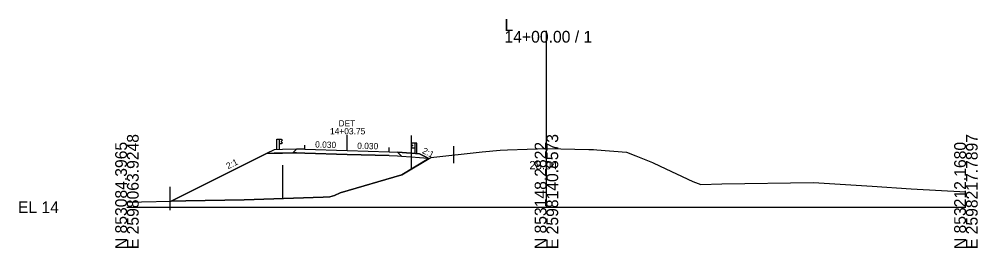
# Model space of a CAD drawing. Extents: x -26 to 1203, y -10 to 9526.
# Drawn here: x -25.7 to 202.8, y 3990.3 to 4044.9 of the extents above; entities that cross this region are included whole.
import ezdxf

# ---------------------------------------------------------------- set-up
doc = ezdxf.new("R2010")
doc.units = 0
for name, color, linetype in [('Exist Cross Section Cell', 7, 'Continuous'), ('Exist XS Center Line Elevation Label', 7, 'Continuous'), ('Exist XS Ground Line', 7, 'Continuous'), ('Prop XS Alignment Label', 7, 'Continuous'), ('Prop XS Earthwork Shape', 7, 'Continuous'), ('Prop XS EOT Tick Mark', 7, 'Continuous'), ('Prop XS Exc Vertical Line 1', 7, 'Continuous'), ('Prop XS Exc Vertical Line 2', 7, 'Continuous'), ('Prop XS Finish Grade', 7, 'Continuous'), ('Prop XS Finish Grade Earthwork', 7, 'Continuous'), ('Prop XS Finish Grade Paved Shoulder', 7, 'Continuous'), ('Prop XS Finish Grade Pavement', 7, 'Continuous'), ('Prop XS Guardrail', 7, 'Continuous'), ('Prop XS Pvmt Edge Slope', 7, 'Continuous'), ('Prop XS SE Text', 7, 'Continuous'), ('Prop XS Side Slope Text', 7, 'Continuous'), ('Prop XS Station Labels', 7, 'Continuous'), ('Prop XS Subgrade Earthwork', 7, 'Continuous'), ('Scratch_Level_1', 7, 'Continuous'), ('Scratch_Level_2', 7, 'Continuous')]:
    doc.layers.add(name, color=color, linetype=linetype)

msp = doc.modelspace()

# ---------------------------------------------------------------- linework, layer by layer
at = {"layer": 'Exist Cross Section Cell'}
for p, q in [((100, 4000), (100, 4042.11)), ((0, 4000), (100, 4000)), ((100, 4000), (200, 4000))]:
    msp.add_line(p, q, dxfattribs=at)
at = {"layer": 'Exist XS Ground Line'}
for p, q in [((72.42, 4011.9), (84.69, 4013.21)), ((84.69, 4013.21), (88.97, 4013.65)), ((88.97, 4013.65), (90.75, 4013.71)), ((90.75, 4013.71), (100.08, 4014.04)), ((100.08, 4014.04), (110.08, 4013.82)), ((110.08, 4013.82), (111.25, 4013.8)), ((111.25, 4013.8), (112.01, 4013.74)), ((112.01, 4013.74), (119.1, 4013.19)), ((119.1, 4013.19), (121.28, 4012.25)), ((65.52, 4007.76), (72.42, 4011.9)), ((121.28, 4012.25), (125.27, 4010.68)), ((125.27, 4010.68), (127.13, 4009.79)), ((127.13, 4009.79), (134.87, 4006.19)), ((50.79, 4003.41), (65.52, 4007.76)), ((134.87, 4006.19), (136.77, 4005.43)), ((136.77, 4005.43), (141.82, 4005.62)), ((141.82, 4005.62), (163.67, 4005.89)), ((163.67, 4005.89), (177.65, 4005.07)), ((177.65, 4005.07), (186.96, 4004.41)), ((186.96, 4004.41), (200, 4003.71)), ((14, 4001.56), (27.91, 4001.74)), ((27.91, 4001.74), (46.81, 4002.42)), ((46.81, 4002.42), (48.33, 4002.47)), ((48.33, 4002.47), (49.49, 4002.8)), ((49.49, 4002.8), (50.79, 4003.41)), ((0, 4001.21), (14, 4001.56))]:
    msp.add_line(p, q, dxfattribs=at)
at = {"layer": 'Prop XS Earthwork Shape'}
msp.add_lwpolyline([(71.84, 4011.72), (71.99, 4011.64), (65.52, 4007.76), (50.79, 4003.41), (49.49, 4002.8), (48.33, 4002.47), (46.81, 4002.42), (27.91, 4001.74), (14, 4001.56), (10.55, 4001.48), (33.23, 4012.82), (35.07, 4012.88), (37.07, 4012.94), (39.54, 4013.01), (40.43, 4012.98), (42.43, 4012.92), (52.46, 4012.62), (62.49, 4012.32), (64.49, 4012.26), (65.44, 4012.23), (67.77, 4012.04), (69.77, 4011.88)], close=True, dxfattribs=at)
at = {"layer": 'Prop XS EOT Tick Mark'}
for p, q in [((42.43, 4013.84), (42.43, 4014.84)), ((62.49, 4013.23), (62.49, 4014.23))]:
    msp.add_line(p, q, dxfattribs=at)
at = {"layer": 'Prop XS Exc Vertical Line 1'}
msp.add_line((10.24, 4004.84), (10.24, 3999.27), dxfattribs=at)
at = {"layer": 'Prop XS Exc Vertical Line 2'}
msp.add_line((77.88, 4014.61), (77.88, 4010.51), dxfattribs=at)
at = {"layer": 'Prop XS Finish Grade'}
for p, q in [((35.07, 4013.74), (33.23, 4012.82)), ((37.07, 4013.8), (35.07, 4013.74)), ((40.43, 4013.9), (37.07, 4013.8)), ((64.49, 4013.17), (67.77, 4012.91)), ((67.77, 4012.91), (69.77, 4012.75)), ((69.77, 4012.75), (71.84, 4011.72))]:
    msp.add_line(p, q, dxfattribs=at)
at = {"layer": 'Prop XS Finish Grade Earthwork'}
for p, q in [((33.23, 4012.82), (10.55, 4001.48)), ((71.84, 4011.72), (71.99, 4011.64))]:
    msp.add_line(p, q, dxfattribs=at)
at = {"layer": 'Prop XS Finish Grade Paved Shoulder'}
for p, q in [((42.43, 4013.84), (40.43, 4013.9)), ((62.49, 4013.23), (64.49, 4013.17))]:
    msp.add_line(p, q, dxfattribs=at)
at = {"layer": 'Prop XS Finish Grade Pavement'}
for p, q in [((42.43, 4013.84), (52.46, 4013.54)), ((52.46, 4013.54), (62.49, 4013.23))]:
    msp.add_line(p, q, dxfattribs=at)
at = {"layer": 'Prop XS Guardrail'}
for p, q in [((35.75, 4016.26), (36.25, 4016.26)), ((35.75, 4013.76), (35.75, 4016.26)), ((36.25, 4016.26), (36.75, 4016.26)), ((36.25, 4016.26), (36.25, 4013.76)), ((36.75, 4016.26), (37.04, 4016.06)), ((37.04, 4015.94), (36.75, 4015.74)), ((36.75, 4015.74), (36.75, 4015.65)), ((36.75, 4015.65), (37.04, 4015.45)), ((37.04, 4015.33), (36.75, 4015.13)), ((37.04, 4016.06), (37.07, 4016)), ((37.07, 4016), (37.04, 4015.94)), ((37.04, 4015.45), (37.07, 4015.39)), ((37.07, 4015.39), (37.04, 4015.33)), ((36.75, 4015.13), (36.25, 4015.13)), ((67.8, 4015.11), (67.77, 4015.05)), ((67.77, 4015.05), (67.8, 4014.99)), ((67.8, 4014.49), (67.77, 4014.43)), ((67.77, 4014.43), (67.8, 4014.37)), ((68.09, 4015.31), (67.8, 4015.11)), ((67.8, 4014.99), (68.09, 4014.79)), ((68.09, 4014.69), (67.8, 4014.49)), ((67.8, 4014.37), (68.09, 4014.17)), ((68.59, 4015.31), (68.09, 4015.31)), ((68.09, 4014.79), (68.09, 4014.69)), ((68.09, 4014.17), (68.59, 4014.17)), ((69.09, 4015.31), (68.59, 4015.31)), ((68.59, 4015.31), (68.59, 4012.81)), ((69.09, 4012.81), (69.09, 4015.31))]:
    msp.add_line(p, q, dxfattribs=at)
at = {"layer": 'Prop XS Pvmt Edge Slope'}
for p, q in [((40.43, 4013.9), (39.54, 4013.01)), ((64.49, 4013.17), (65.44, 4012.23))]:
    msp.add_line(p, q, dxfattribs=at)
at = {"layer": 'Prop XS Side Slope Text'}
msp.add_line((52.46, 4013.54), (52.46, 4017.19), dxfattribs=at)
at = {"layer": 'Prop XS Subgrade Earthwork'}
for p, q in [((35.07, 4012.88), (33.23, 4012.82)), ((37.07, 4012.94), (35.07, 4012.88)), ((39.54, 4013.01), (37.07, 4012.94)), ((40.43, 4012.98), (39.54, 4013.01)), ((42.43, 4012.92), (40.43, 4012.98)), ((52.46, 4012.62), (42.43, 4012.92)), ((62.49, 4012.32), (52.46, 4012.62)), ((62.49, 4012.32), (64.49, 4012.26)), ((64.49, 4012.26), (65.44, 4012.23)), ((65.44, 4012.23), (67.77, 4012.04)), ((67.77, 4012.04), (69.77, 4011.88)), ((69.77, 4011.88), (71.84, 4011.72))]:
    msp.add_line(p, q, dxfattribs=at)
at = {"layer": 'Scratch_Level_1'}
for points in [[(35.07, 4013.74), (33.23, 4012.82), (35.07, 4012.88), (37.07, 4012.94), (39.54, 4013.01), (40.43, 4013.9), (37.07, 4013.8)], [(69.77, 4011.88), (71.84, 4011.72), (69.77, 4012.75), (67.77, 4012.91), (64.49, 4013.17), (65.44, 4012.23), (67.77, 4012.04)]]:
    msp.add_lwpolyline(points, close=True, dxfattribs=at)
at = {"layer": 'Scratch_Level_2'}
for p, q in [((67.77, 4017.11), (67.77, 4009.11)), ((37.06, 4010.07), (37.06, 4002.07))]:
    msp.add_line(p, q, dxfattribs=at)

# ---------------------------------------------------------------- texts
at = {"layer": 'Exist Cross Section Cell'}
for s, p in [('L', (90, 4042.11)), ('14+00.00 / 1', (90, 4039.31)), ('EL 14', (-26, 3998.6))]:
    msp.add_text(s, height=2.8, dxfattribs=at).set_placement(p)
for s, p in [('N 853084.3965', (0, 3990)), ('E 2598063.9248', (2.8, 3990)), ('N 853148.2822', (100, 3990)), ('E 2598140.8573', (102.8, 3990)), ('N 853212.1680', (200, 3990)), ('E 2598217.7897', (202.8, 3990))]:
    msp.add_text(s, height=2.8, rotation=90, dxfattribs=at).set_placement(p)
at = {"layer": 'Exist XS Center Line Elevation Label'}
msp.add_text('28.04', height=2, dxfattribs=at).set_placement((95.93, 4009.04))
at = {"layer": 'Prop XS Alignment Label'}
msp.add_text('DET', height=1.5, dxfattribs=at).set_placement((50.43, 4019.29))
at = {"layer": 'Prop XS SE Text'}
for rotation, p in [(358.2726, (44.84, 4014.27)), (358.2724, (54.87, 4013.96))]:
    msp.add_text('0.030', height=1.5, rotation=rotation, dxfattribs=at).set_placement(p)
at = {"layer": 'Prop XS Side Slope Text'}
for rotation, p in [(333.4349, (70.25, 4013.01)), (26.5651, (24.12, 4009.06))]:
    msp.add_text('2:1', height=1.5, rotation=rotation, dxfattribs=at).set_placement(p)
at = {"layer": 'Prop XS Station Labels'}
msp.add_text('14+03.75', height=1.5, dxfattribs=at).set_placement((48.4, 4017.4))

doc.saveas('drawing.dxf')
